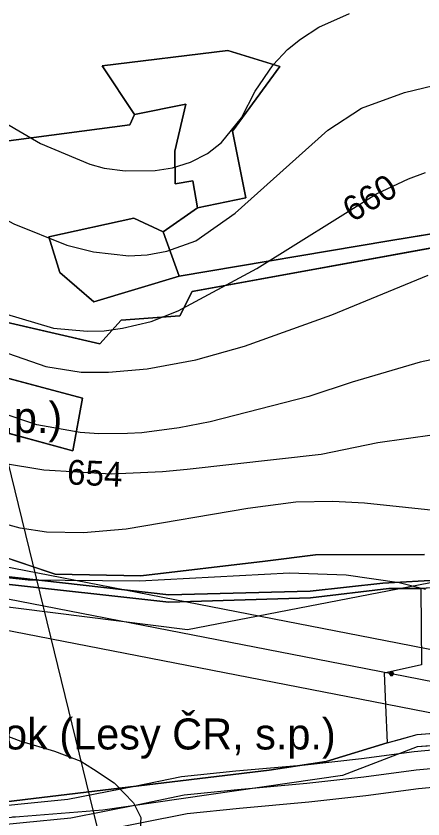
# Model space of a CAD drawing. Extents: x -709418 to -703832, y -1161719 to -1157826.
# Drawn here: x -706474.1 to -706342.8, y -1160852.4 to -1160593.4 of the extents above; entities that cross this region are included whole.
import ezdxf

# ---------------------------------------------------------------- set-up
doc = ezdxf.new("R2010")
doc.units = 0
for name, color, linetype in [('102_obvod PÚ', 7, 'Continuous'), ('120_vrstevnice hlavní', 7, 'Continuous'), ('121_vrstevnice hlavní_popis', 7, 'Continuous'), ('122_vrstevnice základní', 7, 'Continuous'), ('124_vrstevnice doplňková', 7, 'Continuous'), ('206_TTP_KN', 7, 'Continuous'), ('207_lesní pozemek_KN', 7, 'Continuous'), ('208_vodní plocha_KN', 7, 'Continuous'), ('210_ostatní plocha_KN', 7, 'Continuous'), ('501_vodní tok', 7, 'Continuous'), ('502_vodní tok_popis', 7, 'Continuous'), ('514 odvodnění - LPIS', 7, 'Continuous'), ('705_el VN nadzemní_E.ON', 7, 'Continuous'), ('723_radioreléová trasa_UAP', 7, 'Continuous'), ('735_OP sítí TI', 7, 'Continuous')]:
    doc.layers.add(name, color=color, linetype=linetype)

# ---------------------------------------------------------------- blocks, each defined once
blk = doc.blocks.new('Elektro - Implicitní$0$VN4601')
for points in [[(1.23, 0), (1.22, 0.13), (1.2, 0.26), (1.17, 0.38), (1.12, 0.5), (1.06, 0.61), (0.99, 0.72), (0.91, 0.82), (0.82, 0.91), (0.72, 0.99), (0.61, 1.06), (0.5, 1.12), (0.38, 1.17), (0.26, 1.2), (0.13, 1.22), (0, 1.23), (-0.13, 1.22), (-0.26, 1.2), (-0.38, 1.17), (-0.5, 1.12), (-0.61, 1.06), (-0.72, 0.99), (-0.82, 0.91), (-0.91, 0.82), (-0.99, 0.72), (-1.06, 0.61), (-1.12, 0.5), (-1.17, 0.38), (-1.2, 0.26), (-1.22, 0.13), (-1.23, 0), (-1.22, -0.13), (-1.2, -0.26), (-1.17, -0.38), (-1.12, -0.5), (-1.06, -0.61), (-0.99, -0.72), (-0.91, -0.82), (-0.82, -0.91), (-0.72, -0.99), (-0.61, -1.06), (-0.5, -1.12), (-0.38, -1.17), (-0.26, -1.2), (-0.13, -1.22), (0, -1.23), (0.13, -1.22), (0.26, -1.2), (0.38, -1.17), (0.5, -1.12), (0.61, -1.06), (0.72, -0.99), (0.82, -0.91), (0.91, -0.82), (0.99, -0.72), (1.06, -0.61), (1.12, -0.5), (1.17, -0.38), (1.2, -0.26), (1.22, -0.13), (1.23, 0)], [(0.92, 0), (0.92, 0.1), (0.9, 0.19), (0.88, 0.28), (0.84, 0.37), (0.8, 0.46), (0.75, 0.54), (0.68, 0.62), (0.62, 0.68), (0.54, 0.74), (0.46, 0.8), (0.37, 0.84), (0.28, 0.88), (0.19, 0.9), (0.1, 0.92), (0, 0.92), (-0.1, 0.92), (-0.19, 0.9), (-0.28, 0.88), (-0.37, 0.84), (-0.46, 0.8), (-0.54, 0.74), (-0.62, 0.68), (-0.68, 0.62), (-0.75, 0.54), (-0.8, 0.46), (-0.84, 0.37), (-0.88, 0.28), (-0.9, 0.19), (-0.92, 0.1), (-0.92, 0), (-0.92, -0.1), (-0.9, -0.19), (-0.88, -0.29), (-0.84, -0.38), (-0.8, -0.46), (-0.75, -0.54), (-0.68, -0.62), (-0.62, -0.69), (-0.54, -0.75), (-0.46, -0.8), (-0.37, -0.84), (-0.28, -0.88), (-0.19, -0.9), (-0.1, -0.92), (0, -0.92), (0.1, -0.92), (0.19, -0.9), (0.28, -0.88), (0.37, -0.84), (0.46, -0.8), (0.54, -0.75), (0.62, -0.69), (0.68, -0.62), (0.75, -0.54), (0.8, -0.46), (0.84, -0.38), (0.88, -0.29), (0.9, -0.19), (0.92, -0.1), (0.92, 0)], [(0.61, 0), (0.61, 0.06), (0.6, 0.13), (0.58, 0.19), (0.56, 0.25), (0.53, 0.31), (0.5, 0.36), (0.46, 0.41), (0.41, 0.46), (0.36, 0.5), (0.31, 0.53), (0.25, 0.56), (0.19, 0.58), (0.13, 0.6), (0.06, 0.61), (0, 0.61), (-0.06, 0.61), (-0.13, 0.6), (-0.19, 0.58), (-0.25, 0.56), (-0.31, 0.53), (-0.36, 0.5), (-0.41, 0.46), (-0.46, 0.41), (-0.5, 0.36), (-0.53, 0.31), (-0.56, 0.25), (-0.58, 0.19), (-0.6, 0.13), (-0.61, 0.06), (-0.61, 0), (-0.61, -0.07), (-0.6, -0.13), (-0.58, -0.19), (-0.56, -0.25), (-0.53, -0.31), (-0.5, -0.36), (-0.46, -0.41), (-0.41, -0.46), (-0.36, -0.5), (-0.31, -0.53), (-0.25, -0.56), (-0.19, -0.58), (-0.13, -0.6), (-0.06, -0.61), (0, -0.61), (0.06, -0.61), (0.13, -0.6), (0.19, -0.58), (0.25, -0.56), (0.31, -0.53), (0.36, -0.5), (0.41, -0.46), (0.46, -0.41), (0.5, -0.36), (0.53, -0.31), (0.56, -0.25), (0.58, -0.19), (0.6, -0.13), (0.61, -0.06), (0.61, 0)], [(0.31, 0), (0.31, 0.03), (0.3, 0.06), (0.29, 0.09), (0.28, 0.12), (0.27, 0.15), (0.25, 0.18), (0.23, 0.21), (0.21, 0.23), (0.18, 0.25), (0.15, 0.27), (0.12, 0.28), (0.09, 0.29), (0.06, 0.3), (0.03, 0.31), (0, 0.31), (-0.03, 0.31), (-0.06, 0.3), (-0.09, 0.29), (-0.12, 0.28), (-0.15, 0.27), (-0.18, 0.25), (-0.21, 0.23), (-0.23, 0.21), (-0.25, 0.18), (-0.27, 0.15), (-0.28, 0.12), (-0.29, 0.09), (-0.3, 0.06), (-0.31, 0.03), (-0.31, 0), (-0.31, -0.03), (-0.3, -0.06), (-0.29, -0.1), (-0.28, -0.13), (-0.27, -0.15), (-0.25, -0.18), (-0.23, -0.21), (-0.21, -0.23), (-0.18, -0.25), (-0.15, -0.27), (-0.12, -0.28), (-0.09, -0.29), (-0.06, -0.3), (-0.03, -0.31), (0, -0.31), (0.03, -0.31), (0.06, -0.3), (0.09, -0.29), (0.12, -0.28), (0.15, -0.27), (0.18, -0.25), (0.21, -0.23), (0.23, -0.21), (0.25, -0.18), (0.27, -0.15), (0.28, -0.13), (0.29, -0.1), (0.3, -0.06), (0.31, -0.03), (0.31, 0)]]:
    blk.add_lwpolyline(points)

msp = doc.modelspace()

# ---------------------------------------------------------------- linework, layer by layer
at = {"layer": '102_obvod PÚ'}
for points in [[(-706537.25, -1160587.47), (-706483.95, -1160634.67), (-706437.33, -1160628.53), (-706435.81, -1160625.24), (-706446.25, -1160609.53), (-706405.71, -1160604.59), (-706388.94, -1160609.69), (-706404.23, -1160630.57), (-706399.98, -1160652.01), (-706415.48, -1160655.34), (-706426.59, -1160662.98), (-706421.4, -1160677.36), (-706353.84, -1160665.92), (-706212.91, -1160642.8), (-706210.48, -1160628.13), (-706190.31, -1160626.07), (-706166.67, -1160638.53), (-706094.84, -1160616.38)], [(-706094.84, -1160616.38), (-706166.67, -1160638.53), (-706190.31, -1160626.07), (-706210.48, -1160628.13), (-706212.91, -1160642.8), (-706353.84, -1160665.92), (-706421.4, -1160677.36), (-706426.59, -1160662.98), (-706415.48, -1160655.34), (-706399.98, -1160652.01), (-706404.23, -1160630.57), (-706388.94, -1160609.69), (-706405.71, -1160604.59), (-706446.25, -1160609.53), (-706435.81, -1160625.24), (-706437.33, -1160628.53), (-706483.95, -1160634.67), (-706537.25, -1160587.47)], [(-706078.84, -1160616.17), (-706172.32, -1160644.88), (-706186.83, -1160645.94), (-706180.3, -1160673), (-706202.87, -1160669.67), (-706205.21, -1160662.52), (-706201.46, -1160647.52), (-706309.32, -1160662.59), (-706417.2, -1160682.29), (-706421.21, -1160690.13), (-706440.11, -1160691.54), (-706447.05, -1160699.18), (-706482.01, -1160691.05), (-706489.16, -1160699.96), (-706505.86, -1160702.51), (-706452.64, -1160716.67), (-706455.75, -1160733.65), (-706550.59, -1160707.82), (-706565.95, -1160710.65), (-706581.87, -1160708.88), (-706583.78, -1160707.11), (-706585.3, -1160704.67)], [(-706585.3, -1160704.67), (-706583.78, -1160707.11), (-706581.87, -1160708.88), (-706565.95, -1160710.65), (-706550.59, -1160707.82), (-706455.75, -1160733.65), (-706452.64, -1160716.67), (-706505.86, -1160702.51), (-706489.16, -1160699.96), (-706482.01, -1160691.05), (-706447.05, -1160699.18), (-706440.11, -1160691.54), (-706421.21, -1160690.13), (-706417.2, -1160682.29), (-706309.32, -1160662.59), (-706201.46, -1160647.52), (-706205.21, -1160662.52), (-706202.87, -1160669.67), (-706180.3, -1160673), (-706186.83, -1160645.94), (-706172.32, -1160644.88), (-706078.84, -1160616.17)], [(-706132.64, -1160763.73), (-706186.11, -1160775.01), (-706211.95, -1160782.93), (-706228.36, -1160784.79), (-706284.52, -1160780.59), (-706285.11, -1160766.44), (-706317.29, -1160776.61), (-706343.44, -1160778.04), (-706343.3, -1160802.68), (-706355.36, -1160805.32), (-706354.93, -1160815.6), (-706354.36, -1160827.87), (-706344.72, -1160825.16), (-706297.34, -1160821.34), (-706288.53, -1160820.63), (-706288.78, -1160824.8), (-706344.65, -1160829.16), (-706368.79, -1160838.42), (-706446.04, -1160849.6), (-706472.94, -1160851.67), (-706480.86, -1160852.31), (-706505.26, -1160852.31), (-706520.68, -1160919.75)]]:
    msp.add_lwpolyline(points, dxfattribs=at)
at = {"layer": '120_vrstevnice hlavní'}
for points in [[(-706575.65, -1160587.5), (-706562.11, -1160610.3), (-706540.74, -1160638.8), (-706530.91, -1160649.77), (-706511.38, -1160668.87), (-706505.26, -1160673.86), (-706494.43, -1160681.27), (-706483.6, -1160687.11), (-706478.18, -1160689.25), (-706461.94, -1160694.09), (-706451.11, -1160695.09), (-706445.6, -1160694.97), (-706439.71, -1160694.09), (-706430.47, -1160691.96), (-706421.75, -1160688.53), (-706396.39, -1160674.85), (-706357.77, -1160650.77), (-706347.51, -1160645.93), (-706341.96, -1160643.93)], [(-706620.39, -1160694.8), (-706577.64, -1160723.87), (-706548.72, -1160745.1), (-706532.9, -1160755.79), (-706517.22, -1160764.77), (-706512.95, -1160766.62), (-706495.85, -1160771.46), (-706483.03, -1160773.89), (-706470.2, -1160775.31), (-706434.29, -1160775.6), (-706385.85, -1160773.03), (-706367.61, -1160773.6), (-706350.51, -1160776.17), (-706341.96, -1160778.3)]]:
    msp.add_lwpolyline(points, dxfattribs=at)
at = {"layer": '122_vrstevnice základní'}
for points in [[(-706558.26, -1160573.54), (-706543.44, -1160595.48), (-706522.93, -1160618.85), (-706509.96, -1160634.53), (-706495.42, -1160648.21), (-706486.16, -1160654.33), (-706474.76, -1160660.46), (-706457.66, -1160667.3), (-706449.11, -1160669.44), (-706437.71, -1160670.72), (-706431.73, -1160670.44), (-706425.46, -1160669.3), (-706416.05, -1160665.88), (-706403.37, -1160657.04), (-706373.45, -1160630.25), (-706362.67, -1160623.11), (-706348.8, -1160618.14), (-706339.39, -1160615.86)], [(-706527.63, -1160580.38), (-706501.55, -1160604.46), (-706485.45, -1160621.28), (-706477.61, -1160627.83), (-706466.21, -1160634.53), (-706450.25, -1160641.22), (-706445.69, -1160642.51), (-706438.85, -1160643.36), (-706429.14, -1160643.21), (-706423.59, -1160642.35), (-706417.76, -1160640.51), (-706412.35, -1160637.8), (-706407.79, -1160634.24), (-706401.38, -1160626.26), (-706396.96, -1160617.71), (-706391.12, -1160609.16), (-706386.46, -1160604.18), (-706382.28, -1160600.9), (-706376.44, -1160597.05), (-706366.47, -1160592.63)], [(-706605, -1160583.8), (-706592.89, -1160602.61), (-706574.51, -1160625.41), (-706552.99, -1160648.78), (-706510.1, -1160683.97), (-706495.85, -1160693.52), (-706481.6, -1160700.5), (-706464.5, -1160706.49), (-706453.1, -1160708.34), (-706444.27, -1160708.34), (-706431.73, -1160707.2), (-706416.05, -1160704.35), (-706400.38, -1160699.93), (-706372.17, -1160689.81), (-706341.1, -1160676.99)], [(-706334.03, -1160702.99), (-706343.67, -1160705.06), (-706365.61, -1160711.47), (-706379.58, -1160716.18), (-706411.49, -1160724.3), (-706421.47, -1160726.29), (-706433.44, -1160727.86), (-706438.09, -1160728.08), (-706447.4, -1160728.15), (-706453.39, -1160727.72), (-706467.35, -1160725.3), (-706479.32, -1160721.31), (-706493.29, -1160714.61), (-706508.11, -1160705.06), (-706528.2, -1160688.68), (-706578.5, -1160645.07), (-706608.71, -1160616.15)], [(-706608.28, -1160637.52), (-706586.87, -1160660.09), (-706570.66, -1160677.13), (-706552.71, -1160694.52), (-706541.02, -1160702.93), (-706513.95, -1160723.44), (-706503.38, -1160729.2), (-706495.85, -1160732.56), (-706478.75, -1160737.55), (-706465.07, -1160739.83), (-706443.41, -1160741.11), (-706426.84, -1160740.36), (-706418.9, -1160739.55), (-706375.59, -1160734.7), (-706357.35, -1160731), (-706339.11, -1160728.43)], [(-706324, -1160754.51), (-706361.62, -1160750.52), (-706371.9, -1160750.02), (-706383.85, -1160750.23), (-706399.24, -1160752.23), (-706438.57, -1160758.93), (-706452.25, -1160760.06), (-706464.22, -1160759.92), (-706472.77, -1160758.64), (-706482.69, -1160755.91), (-706490.15, -1160753.08), (-706500.92, -1160747.51), (-706507.11, -1160743.68), (-706545.58, -1160717.89), (-706561.83, -1160705.92), (-706573.37, -1160697.8), (-706584.2, -1160689.96), (-706595.31, -1160680.55), (-706605.29, -1160673.14), (-706656.59, -1160639.66)]]:
    msp.add_lwpolyline(points, dxfattribs=at)
at = {"layer": '124_vrstevnice doplňková'}
msp.add_lwpolyline([(-706558.01, -1160764.02), (-706551.42, -1160768.33), (-706539.31, -1160778.3), (-706532.19, -1160785.86), (-706525.21, -1160794.83), (-706517.65, -1160802.81), (-706505.97, -1160811.08), (-706486.45, -1160822.05), (-706472.48, -1160827.32), (-706461.67, -1160830.53), (-706453.13, -1160833.79), (-706449.11, -1160836.3), (-706442.42, -1160840.72), (-706436.19, -1160847.18), (-706433.82, -1160851.92), (-706434.25, -1160859.11)], dxfattribs=at)
at = {"layer": '206_TTP_KN'}
for p, q in [((-706417.2, -1160682.29), (-706309.32, -1160662.59)), ((-706421.21, -1160690.13), (-706417.2, -1160682.29)), ((-706440.11, -1160691.54), (-706421.21, -1160690.13)), ((-706482.01, -1160691.05), (-706447.05, -1160699.18)), ((-706447.05, -1160699.18), (-706440.11, -1160691.54)), ((-706452.64, -1160716.67), (-706505.86, -1160702.51)), ((-706455.75, -1160733.65), (-706452.64, -1160716.67)), ((-706491, -1160723.96), (-706455.75, -1160733.65)), ((-706461.39, -1160773.42), (-706492.81, -1160763.05)), ((-706377.45, -1160767.19), (-706393.73, -1160769.21)), ((-706342.31, -1160767.05), (-706377.45, -1160767.19)), ((-706393.73, -1160769.21), (-706433.79, -1160773.92)), ((-706433.79, -1160773.92), (-706461.39, -1160773.42))]:
    msp.add_line(p, q, dxfattribs=at)
msp.add_lwpolyline([(-706094.84, -1160616.38), (-706166.67, -1160638.53), (-706190.31, -1160626.07), (-706210.48, -1160628.13), (-706212.91, -1160642.8), (-706353.84, -1160665.92), (-706421.4, -1160677.36), (-706426.59, -1160662.98), (-706415.48, -1160655.34), (-706399.98, -1160652.01), (-706404.23, -1160630.57), (-706388.94, -1160609.69), (-706405.71, -1160604.59), (-706446.25, -1160609.53), (-706435.81, -1160625.24), (-706437.33, -1160628.53), (-706483.95, -1160634.67), (-706537.25, -1160587.47)], dxfattribs=at)
at = {"layer": '207_lesní pozemek_KN'}
for p, q in [((-706446.25, -1160609.53), (-706405.71, -1160604.59)), ((-706405.71, -1160604.59), (-706388.94, -1160609.69)), ((-706435.81, -1160625.24), (-706446.25, -1160609.53)), ((-706388.94, -1160609.69), (-706404.23, -1160630.57)), ((-706435.81, -1160625.24), (-706419.3, -1160621.83)), ((-706419.3, -1160621.83), (-706435.81, -1160625.24)), ((-706419.3, -1160621.83), (-706422.84, -1160636.97)), ((-706422.84, -1160636.97), (-706419.3, -1160621.83)), ((-706437.33, -1160628.53), (-706435.81, -1160625.24)), ((-706483.95, -1160634.67), (-706437.33, -1160628.53)), ((-706404.23, -1160630.57), (-706399.98, -1160652.01)), ((-706422.84, -1160636.97), (-706422.7, -1160647.59)), ((-706422.7, -1160647.59), (-706422.84, -1160636.97)), ((-706353.84, -1160665.92), (-706212.91, -1160642.8)), ((-706422.7, -1160647.59), (-706417.04, -1160646.6)), ((-706417.04, -1160646.6), (-706422.7, -1160647.59)), ((-706417.04, -1160646.6), (-706415.48, -1160655.34)), ((-706415.48, -1160655.34), (-706417.04, -1160646.6)), ((-706399.98, -1160652.01), (-706415.48, -1160655.34)), ((-706415.48, -1160655.34), (-706426.59, -1160662.98)), ((-706436.02, -1160658.61), (-706463.52, -1160664.59)), ((-706463.52, -1160664.59), (-706436.02, -1160658.61)), ((-706426.59, -1160662.98), (-706436.02, -1160658.61)), ((-706436.02, -1160658.61), (-706426.59, -1160662.98)), ((-706463.52, -1160664.59), (-706459.96, -1160676.18)), ((-706459.96, -1160676.18), (-706463.52, -1160664.59)), ((-706426.59, -1160662.98), (-706421.4, -1160677.36)), ((-706309.32, -1160662.59), (-706417.2, -1160682.29)), ((-706421.4, -1160677.36), (-706353.84, -1160665.92)), ((-706459.96, -1160676.18), (-706448.99, -1160685.6)), ((-706448.99, -1160685.6), (-706459.96, -1160676.18)), ((-706448.99, -1160685.6), (-706421.4, -1160677.36)), ((-706421.4, -1160677.36), (-706448.99, -1160685.6)), ((-706417.2, -1160682.29), (-706421.21, -1160690.13)), ((-706421.21, -1160690.13), (-706440.11, -1160691.54)), ((-706447.05, -1160699.18), (-706482.01, -1160691.05)), ((-706440.11, -1160691.54), (-706447.05, -1160699.18)), ((-706505.86, -1160702.51), (-706452.64, -1160716.67)), ((-706452.64, -1160716.67), (-706455.75, -1160733.65)), ((-706455.75, -1160733.65), (-706491, -1160723.96))]:
    msp.add_line(p, q, dxfattribs=at)
at = {"layer": '208_vodní plocha_KN'}
for p, q in [((-706344.72, -1160825.16), (-706297.34, -1160821.34)), ((-706349.15, -1160826.41), (-706344.72, -1160825.16)), ((-706288.78, -1160824.8), (-706344.65, -1160829.16)), ((-706374.07, -1160833.86), (-706354.36, -1160827.87)), ((-706354.36, -1160827.87), (-706349.15, -1160826.41)), ((-706344.65, -1160829.16), (-706368.79, -1160838.42)), ((-706392.37, -1160836.66), (-706374.07, -1160833.86)), ((-706482.83, -1160847.47), (-706392.37, -1160836.66)), ((-706368.79, -1160838.42), (-706446.04, -1160849.6)), ((-706446.04, -1160849.6), (-706472.94, -1160851.67)), ((-706472.94, -1160851.67), (-706475.18, -1160851.85))]:
    msp.add_line(p, q, dxfattribs=at)
at = {"layer": '210_ostatní plocha_KN'}
for p, q in [((-706492.81, -1160763.05), (-706461.39, -1160773.42)), ((-706393.73, -1160769.21), (-706377.45, -1160767.19)), ((-706377.45, -1160767.19), (-706342.31, -1160767.05)), ((-706433.79, -1160773.92), (-706393.73, -1160769.21)), ((-706482.86, -1160773.55), (-706424.8, -1160780.15)), ((-706424.8, -1160780.15), (-706482.86, -1160773.55)), ((-706461.39, -1160773.42), (-706433.79, -1160773.92)), ((-706424.8, -1160782.5), (-706482.83, -1160776.06)), ((-706482.83, -1160776.06), (-706424.8, -1160782.5)), ((-706355.76, -1160776.33), (-706320.98, -1160774.45)), ((-706320.98, -1160774.45), (-706355.76, -1160776.33)), ((-706379.16, -1160778.95), (-706355.76, -1160776.33)), ((-706355.76, -1160776.33), (-706379.16, -1160778.95)), ((-706353.81, -1160778.11), (-706379.08, -1160781.08)), ((-706379.08, -1160781.08), (-706353.81, -1160778.11)), ((-706343.44, -1160778.04), (-706353.81, -1160778.11)), ((-706353.81, -1160778.11), (-706343.44, -1160778.04)), ((-706317.29, -1160776.61), (-706343.44, -1160778.04)), ((-706343.44, -1160778.04), (-706343.3, -1160802.68)), ((-706424.8, -1160780.15), (-706379.16, -1160778.95)), ((-706379.16, -1160778.95), (-706424.8, -1160780.15)), ((-706379.08, -1160781.08), (-706424.8, -1160782.5)), ((-706424.8, -1160782.5), (-706379.08, -1160781.08)), ((-706343.3, -1160802.68), (-706355.36, -1160805.32)), ((-706355.36, -1160805.32), (-706354.93, -1160815.6)), ((-706354.93, -1160815.6), (-706354.36, -1160827.87)), ((-706354.36, -1160827.87), (-706374.07, -1160833.86)), ((-706374.07, -1160833.86), (-706392.37, -1160836.66)), ((-706392.37, -1160836.66), (-706482.83, -1160847.47))]:
    msp.add_line(p, q, dxfattribs=at)
at = {"layer": '501_vodní tok'}
msp.add_lwpolyline([(-706294.74, -1160832), (-706344.96, -1160836.67), (-706361.92, -1160838.95), (-706380.23, -1160840.97), (-706402.58, -1160842.99), (-706419.81, -1160844.75), (-706434.62, -1160847.79), (-706456.43, -1160852.08), (-706471.78, -1160853.59), (-706489.01, -1160855.36), (-706503.02, -1160854.6), (-706551.76, -1160849.8), (-706594.84, -1160844.25), (-706638.19, -1160837.68), (-706729.87, -1160806.74), (-706754.65, -1160798.66), (-706775.37, -1160792.42), (-706776.87, -1160792.14)], dxfattribs=at)
at = {"layer": '514 odvodnění - LPIS'}
msp.add_lwpolyline([(-706863.97, -1160871.89), (-706791.27, -1160822.65), (-706735.19, -1160778.33), (-706748.47, -1160726.66), (-706643.11, -1160716.97), (-706567.25, -1160738.96), (-706484.44, -1160782.97), (-706418.79, -1160791.25), (-706025.59, -1160715.24)], dxfattribs=at)
at = {"layer": '705_el VN nadzemní_E.ON'}
msp.add_lwpolyline([(-706126.79, -1160947.26), (-706166.94, -1160904.58), (-706239.08, -1160827.82), (-706352.93, -1160805.53), (-706485.08, -1160779.84), (-706590.79, -1160759.31), (-706626.96, -1160690.96), (-706657.04, -1160633.68)], dxfattribs=at)
at = {"layer": '723_radioreléová trasa_UAP'}
msp.add_lwpolyline([(-707182.2, -1157850.62), (-706271.36, -1161577.76)], dxfattribs=at)
at = {"layer": '735_OP sítí TI'}
for points in [[(-706119.51, -1160940.41), (-706159.66, -1160897.73), (-706234, -1160818.62), (-706351.01, -1160795.71), (-706483.17, -1160770.02), (-706584.19, -1160750.4), (-706618.11, -1160686.3), (-706648.19, -1160629.03)], [(-706134.08, -1160954.11), (-706174.22, -1160911.43), (-706244.16, -1160837.01), (-706354.84, -1160815.34), (-706486.99, -1160789.66), (-706597.39, -1160768.21), (-706635.81, -1160695.62), (-706665.89, -1160638.33)], [(-706294.18, -1160837.97), (-706344.28, -1160842.63), (-706361.19, -1160844.9), (-706379.63, -1160846.94), (-706402, -1160848.96), (-706418.9, -1160850.69), (-706433.44, -1160853.67), (-706455.56, -1160858.02), (-706471.18, -1160859.56), (-706488.87, -1160861.38), (-706503.47, -1160860.59), (-706552.43, -1160855.77), (-706595.67, -1160850.19), (-706639.61, -1160843.53), (-706731.76, -1160812.44), (-706756.44, -1160804.39), (-706776.8, -1160798.25), (-706777.98, -1160798.03)], [(-706295.29, -1160826.03), (-706345.63, -1160830.71), (-706362.65, -1160832.99), (-706380.83, -1160835), (-706403.16, -1160837.01), (-706420.72, -1160838.82), (-706435.8, -1160841.9), (-706457.31, -1160846.14), (-706472.38, -1160847.62), (-706489.16, -1160849.34), (-706502.56, -1160848.62), (-706551.08, -1160843.84), (-706594.01, -1160838.31), (-706636.77, -1160831.83), (-706727.98, -1160801.05), (-706728.04, -1160801.03)]]:
    msp.add_lwpolyline(points, dxfattribs=at)

# ---------------------------------------------------------------- block references
at = {"layer": '705_el VN nadzemní_E.ON', "xscale": 0.49999999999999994, "yscale": 0.5000000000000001, "rotation": -11.430305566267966}
msp.add_blockref('Elektro - Implicitní$0$VN4601', (-706352.93, -1160805.53), dxfattribs=at)

# ---------------------------------------------------------------- texts
at = {"layer": '121_vrstevnice hlavní_popis'}
for s, rotation, p in [('660', 31.6194, (-706365.51, -1160660.13)), ('654', 357.3091, (-706457.75, -1160744.45))]:
    msp.add_text(s, height=8, rotation=rotation, dxfattribs=at).set_placement(p)
at = {"layer": '502_vodní tok_popis'}
for s, p in [('Bezejmenný vodní tok 04 (Lesy ČR, s.p.)', (-706702.19, -1160727.87)), ('Kunějovský potok (Lesy ČR, s.p.)', (-706568.63, -1160829.97))]:
    msp.add_text(s, height=10, dxfattribs=at).set_placement(p)

doc.saveas('drawing.dxf')
